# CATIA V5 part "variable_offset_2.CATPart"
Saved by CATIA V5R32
Part number: Part1
Bounding box of the stored display mesh (mm): x -92.294 to 37.025, y -35 to 35, z -60.324 to 55.06
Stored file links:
  D:\PROJECTS\Project 2022\CATIA V5 6R 2022\Resources\Part Files\c17_catia_v6_6r2022_prt\variable_offset_2.CATPart
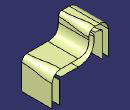
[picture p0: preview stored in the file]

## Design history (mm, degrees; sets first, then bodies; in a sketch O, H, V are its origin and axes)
Set1
  Sketch1 on zx-plane, origin (0, 0, 0), H (-1, 0, 0), V (0, 0, 1)
    point P1 (47.2937, 55.0598)
    line L1 (47.2937, 55.0598) -> (92.2937, 55.0598)
    line L2 (92.2937, 55.0598) -> (92.2937, -19.9402)
    length L2 = 75
    length L1 = 45
    horizontal: L1 H
    vertical: L2 V
  Extrude1: Element1 Sketch1, Lim1 35, Lim2 35
  Sketch2 on zx-plane, origin (0, 0, 0), H (-1, 0, 0), V (0, 0, 1)
    point P1 (47.2937, 55.0598)
    line L1 (47.2937, 55.0598) -> (47.2937, 35.0598)
    reference projected point E1 (47.2937, 55.0598) from Sketch1.P1
    length L1 = 20
    vertical: L1 V
    coincidence: P1 E1
  Extrude2: Element1 Sketch2, Lim1 35, Lim2 35
  Sketch3 on zx-plane, origin (0, 0, 0), H (-1, 0, 0), V (0, 0, 1)
    line L1 (22.975, 9.6765) -> (-37.025, 9.6765)
    line L2 (-37.025, 9.6765) -> (-37.025, -60.3235)
    length L1 = 60
    length L2 = 70
    horizontal: L1 H
    vertical: L2 V
  Extrude3: Element1 Sketch3, Lim1 35, Lim2 35
  Blend1: StartLimit {blendlimit Curve edge of Extrude2, Support Extrude2}, EndLimit {blendlimit Curve edge of Extrude3, Support Extrude3}
  Fillet1: radius 20, on edge [face of Extrude1 from Sketch1.L2 | face of Extrude1 from Sketch1.L1]
  Join1: Elements (Extrude2; Fillet1)
  Fillet2: radius 8, on edge [face of Extrude1 from Sketch1.L1 | face of Extrude2 from Sketch2.L1]
  Fillet3: radius 15, on edge [face of Extrude3 from Sketch3.L1 | face of Extrude3 from Sketch3.L2]
  Join2: Elements (Fillet3; Blend1; Fillet2)
  GSOVariableOffset1: GlobalSurface Join2, TrickyFaces (face of Fillet2; face of Fillet3), ListOfConstraints Blend1
Body1 (main body)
